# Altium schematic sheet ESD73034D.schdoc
size 127 x 101 mm
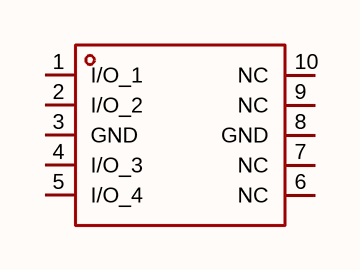
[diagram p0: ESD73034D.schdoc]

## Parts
D?  esd73034d  [DFN-10_L2.5-W1.0-P0.50-BL-2]  (value not drawn)

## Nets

Not connected (* = marked no-connect by the designer): D? 1(I/O_1) 2(I/O_2) 3(GND) 4(I/O_3) 5(I/O_4) 6(NC) 7(NC) 8(GND) 9(NC) 10(NC)

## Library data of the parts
D? = esd73034d: 极性:双向;反向截止电压(Vrwm):3.3V;钳位电压:18V;峰值脉冲电流(Ipp):3A@8/20us;峰值脉冲功率(Ppp):60W@8/20us;击穿电压(VBR):8.5V;; Manufacturer: TECH PUBLIC(台舟); AddInBom: yes; ModelId: bdfd66bff1204c318d65223fd39cc645; ModelTransform: 40.1574,98.8187,0,90,0,0,0,0,0; Polarity: 双向; Reverse Stand-Off Voltage (Vrwm): 3.3V; Clamping Voltage: 18V; Voltage - Breakdown: 8.5V; Reverse Leakage Current (Ir): 200nA; Number of Channels: 四路; level of protection: IEC 61000-4-5；IEC 61000-4-2; Type: ESD; Junction Capacitance: 0.25pF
